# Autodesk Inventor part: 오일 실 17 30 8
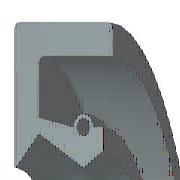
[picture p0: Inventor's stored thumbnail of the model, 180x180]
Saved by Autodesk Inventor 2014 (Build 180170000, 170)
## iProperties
IsCustomPart: 1
Created: 2012-02
Part Number: 오일 실 17 30 8
Material: 고무
Description: 오일-실
Document SubType Name: Modeling
Standard: KS B 2804
Designer: mduedu
Standards Organization: KS
Language: ko-KR
Size Designation: D - 17 30 8
Categories: <MemberInstance><Categories><Category DisplayName="샤프트 부품" InternalName="7f7aeb1f-a693-4053-b835-cee3144e0d98" Mnemonic="SHFT"><Category DisplayName="실링" Intern
Density: 0.93 g/cm^3
Appearance: 고무 - 검은색 - 버전 1.1
Author: mduedu
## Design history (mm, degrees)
revolve "본체" stored, may be unused: angle "d17" = 90 deg
revolve "스프링1" stored, may be unused: angle "d18" = 90 deg
body "Solid1"
sketch "스케치1"
  geometry: L1 (0, 15)-(8, 15); L2 (8, 13.25)-(1.75, 13.25); L3 (1.75, 10.25)-(4.9, 8.5); L4 (4.9, 8.5)-(0, 8.5); L5 (0, 0)-(9.586, 0) reference; L6 (4.9, 8.5)-(6.3, 9.375); L7 (0, 18)-(0, -3) reference; L8 (-1.941, 0)-(11.507, 0) reference; L9 (4.2, 10.6)-(1.75, 11.21); L10 (1.75, 11.21)-(1.75, 13.25); L11 (0, 15)-(0, 8.588); L12 (4.9, 8.5)-(0, 8.5); L13 (1.75, 10.25)-(0.152, 8.528); L14 (8, 15)-(8, 13.25); L15 (5.6, 10.6)-(6.3, 10.6); L16 (6.3, 10.6)-(6.3, 9.375); C1 r 0.455 at (4.9, 10.6); A1 r 0.7 centre (4.9, 10.6) between (5.6, 10.6) and (4.2, 10.6); A2 r 0.088 centre (0.088, 8.588) between (0, 8.588) and (0.152, 8.528); 1 further point
  constraints: 28 end point, 5 horizontal alignment, 5 point on line, 4 point on circle, 4 vertical alignment, 3 centre point, 3 tangent, 2 collinear, 2 horizontal, 2 perpendicular, 1 coincident, 1 parallel
  dimensions: "d0" = 30 diameter of L1 L5 (= SD2); "d1" = 1.75 distance of L1.end L2.start (= SD); "d2" = 0.91 diameter of C1 (= SPDI); "d3" = 1.4 diameter of A1 (= SPDA); "d4" = 17 diameter of L3.end L5 (= NND); "d5" = 20.5 diameter of L3.start L5 (= TKDM); "d7" = 22.42 diameter of L9.end L5 (= TKDM + 0.24 x SWDT); "d8" = 1.75 distance between parallel lines of L11 L10 (= SD); "d9" = 4.9 distance from line of L11 C1.centre (= SPDST); "d10" = 21.2 diameter of C1.centre L5 (= HLDM); "d11" = 0.0875 radius of A2 (= 0.25 x LAB); "d12" = 6.3 distance between parallel lines of L11 L16 (= SDI); "d13" = 18.75 diameter of L6.end L5 (= ABDM); "d14" = 8 distance from line of L11 L1.end (= SWDT)
fillet "모깎기1" dims "d6" = 0.3 (= RR)
other parameters: "SD2" = 30 [user parameter; used in 1 equation term], "SWDT" = 8 [user parameter; used in 2 equation terms], "RR" = 0.3 [user parameter; used in 1 equation term], "SD" = 1.75 [user parameter; used in 2 equation terms], "NND" = 17 [user parameter; used in 1 equation term], "SPDA" = 1.4 [user parameter; used in 1 equation term], "SPDI" = 0.91 [user parameter; used in 1 equation term], "TKDM" = 20.5 [user parameter; used in 2 equation terms], "HLDM" = 21.2 [user parameter; used in 1 equation term], "ABDM" = 18.75 [user parameter; used in 1 equation term], "SDI" = 6.3 [user parameter; used in 1 equation term], "SPDST" = 4.9 [user parameter; used in 1 equation term], "LAB" = 0.35 [user parameter; used in 1 equation term], "d15" = 0, "d16" = 0, "d19" = 0
